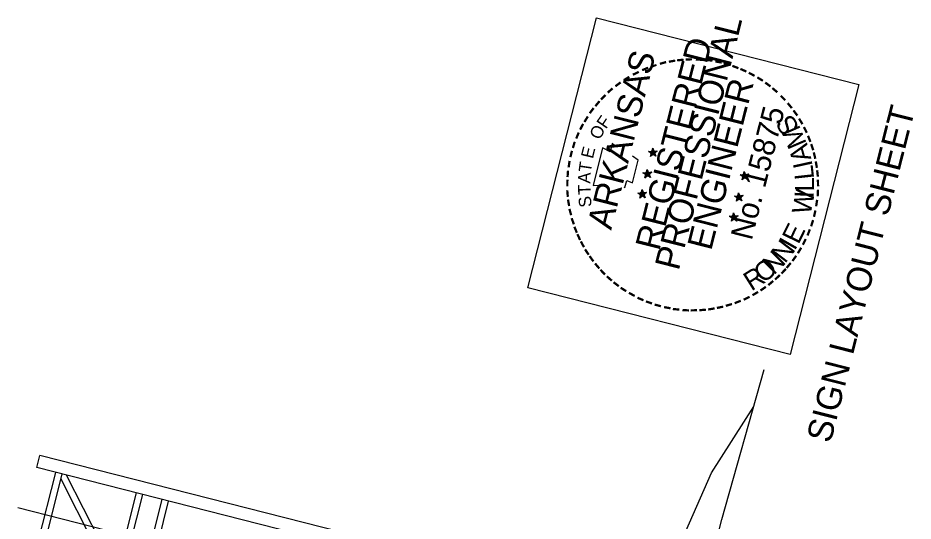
# Model space of a CAD drawing. Extents: x 670006 to 670131, y 737833 to 738003.
# Drawn here: x 670085.91 to 670130.78, y 737959.35 to 737984.55 of the extents above; entities that cross this region are included whole.
import ezdxf

# ---------------------------------------------------------------- set-up
doc = ezdxf.new("R2010")
doc.units = 0
for name, color, linetype in [('R_Border Notes', 7, 'Continuous'), ('R_Border PE', 7, 'Continuous'), ('R_Border Prem', 7, 'Continuous'), ('R_Exist Surface', 7, 'Continuous'), ('R_Fin Surface', 7, 'Continuous'), ('R_SIGN', 7, 'Continuous')]:
    doc.layers.add(name, color=color, linetype=linetype)

msp = doc.modelspace()

# ---------------------------------------------------------------- linework, layer by layer
at = {"layer": 'R_Border PE'}
for p, q in [((670117.518, 737977.86), (670117.681, 737977.864)), ((670117.736, 737977.805), (670117.518, 737977.86)), ((670117.518, 737977.86), (670117.678, 737977.852)), ((670117.518, 737977.86), (670117.667, 737977.836)), ((670117.518, 737977.86), (670117.667, 737977.81)), ((670117.518, 737977.86), (670117.664, 737977.798)), ((670117.518, 737977.86), (670117.655, 737977.787)), ((670117.724, 737978.034), (670117.688, 737977.843)), ((670117.724, 737978.034), (670117.709, 737977.851)), ((670117.724, 737978.034), (670117.721, 737977.848)), ((670117.724, 737978.034), (670117.736, 737977.805)), ((670117.724, 737978.034), (670117.744, 737977.887)), ((670117.724, 737978.034), (670117.752, 737977.891)), ((670117.724, 737978.034), (670117.761, 737977.902)), ((670117.95, 737977.886), (670117.736, 737977.805)), ((670117.95, 737977.886), (670117.755, 737977.852)), ((670117.95, 737977.886), (670117.758, 737977.864)), ((670117.95, 737977.886), (670117.778, 737977.84)), ((670117.95, 737977.886), (670117.785, 737977.793)), ((670117.95, 737977.886), (670117.797, 737977.816)), ((670117.95, 737977.886), (670117.803, 737977.788)), ((670117.616, 737977.61), (670117.736, 737977.805)), ((670117.616, 737977.61), (670117.674, 737977.763)), ((670117.616, 737977.61), (670117.685, 737977.754)), ((670117.616, 737977.61), (670117.691, 737977.752)), ((670117.616, 737977.61), (670117.713, 737977.74)), ((670117.616, 737977.61), (670117.726, 737977.737)), ((670117.616, 737977.61), (670117.738, 737977.734)), ((670117.884, 737977.626), (670117.733, 737977.741)), ((670117.884, 737977.626), (670117.736, 737977.805)), ((670117.884, 737977.626), (670117.753, 737977.743)), ((670117.884, 737977.626), (670117.762, 737977.753)), ((670117.884, 737977.626), (670117.785, 737977.793)), ((670117.884, 737977.626), (670117.785, 737977.767)), ((670117.884, 737977.626), (670117.805, 737977.794)), ((670117.446, 737976.963), (670117.41, 737976.772)), ((670117.446, 737976.963), (670117.431, 737976.78)), ((670117.446, 737976.963), (670117.443, 737976.777)), ((670117.446, 737976.963), (670117.458, 737976.734)), ((670117.446, 737976.963), (670117.466, 737976.816)), ((670117.446, 737976.963), (670117.475, 737976.827)), ((670117.446, 737976.963), (670117.483, 737976.831)), ((670117.234, 737976.791), (670117.403, 737976.794)), ((670117.458, 737976.734), (670117.234, 737976.791)), ((670117.234, 737976.791), (670117.393, 737976.783)), ((670117.234, 737976.791), (670117.389, 737976.765)), ((670117.234, 737976.791), (670117.383, 737976.741)), ((670117.234, 737976.791), (670117.386, 737976.727)), ((670117.234, 737976.791), (670117.378, 737976.722)), ((670117.338, 737976.539), (670117.458, 737976.734)), ((670117.338, 737976.539), (670117.39, 737976.694)), ((670117.338, 737976.539), (670117.402, 737976.691)), ((670117.338, 737976.539), (670117.413, 737976.681)), ((670117.338, 737976.539), (670117.435, 737976.669)), ((670117.338, 737976.539), (670117.448, 737976.666)), ((670117.338, 737976.539), (670117.46, 737976.663)), ((670117.608, 737976.561), (670117.455, 737976.671)), ((670117.674, 737976.822), (670117.458, 737976.734)), ((670117.608, 737976.561), (670117.458, 737976.734)), ((670117.674, 737976.822), (670117.474, 737976.795)), ((670117.608, 737976.561), (670117.475, 737976.672)), ((670117.674, 737976.822), (670117.477, 737976.781)), ((670117.608, 737976.561), (670117.484, 737976.683)), ((670117.674, 737976.822), (670117.499, 737976.769)), ((670117.674, 737976.822), (670117.507, 737976.722)), ((670117.608, 737976.561), (670117.507, 737976.722)), ((670117.608, 737976.561), (670117.507, 737976.696)), ((670117.674, 737976.822), (670117.519, 737976.745)), ((670117.674, 737976.822), (670117.525, 737976.717)), ((670117.608, 737976.561), (670117.527, 737976.724)), ((670122.323, 737976.642), (670122.104, 737976.697)), ((670122.104, 737976.697), (670122.265, 737976.695)), ((670122.104, 737976.697), (670122.264, 737976.689)), ((670122.104, 737976.697), (670122.259, 737976.671)), ((670122.104, 737976.697), (670122.253, 737976.647)), ((670122.104, 737976.697), (670122.25, 737976.635)), ((670122.104, 737976.697), (670122.247, 737976.623)), ((670122.202, 737976.447), (670122.323, 737976.642)), ((670122.202, 737976.447), (670122.259, 737976.594)), ((670122.202, 737976.447), (670122.271, 737976.591)), ((670122.202, 737976.447), (670122.281, 737976.581)), ((670122.202, 737976.447), (670122.3, 737976.577)), ((670122.202, 737976.447), (670122.316, 737976.566)), ((670122.202, 737976.447), (670122.328, 737976.563)), ((670122.308, 737976.865), (670122.274, 737976.68)), ((670122.308, 737976.865), (670122.295, 737976.688)), ((670122.308, 737976.865), (670122.307, 737976.684)), ((670122.308, 737976.865), (670122.323, 737976.642)), ((670122.308, 737976.865), (670122.329, 737976.718)), ((670122.308, 737976.865), (670122.344, 737976.727)), ((670122.308, 737976.865), (670122.352, 737976.731)), ((670122.47, 737976.463), (670122.318, 737976.572)), ((670122.537, 737976.723), (670122.323, 737976.642)), ((670122.47, 737976.463), (670122.323, 737976.642)), ((670122.537, 737976.723), (670122.339, 737976.683)), ((670122.537, 737976.723), (670122.342, 737976.695)), ((670122.47, 737976.463), (670122.343, 737976.572)), ((670122.47, 737976.463), (670122.354, 737976.589)), ((670122.537, 737976.723), (670122.368, 737976.669)), ((670122.47, 737976.463), (670122.371, 737976.604)), ((670122.537, 737976.723), (670122.375, 737976.622)), ((670122.47, 737976.463), (670122.375, 737976.622)), ((670122.537, 737976.723), (670122.382, 737976.646)), ((670122.47, 737976.463), (670122.389, 737976.625)), ((670122.537, 737976.723), (670122.394, 737976.617)), ((670116.978, 737975.779), (670117.146, 737975.782)), ((670117.202, 737975.723), (670116.978, 737975.779)), ((670116.978, 737975.779), (670117.137, 737975.771)), ((670116.978, 737975.779), (670117.134, 737975.759)), ((670116.978, 737975.779), (670117.128, 737975.735)), ((670116.978, 737975.779), (670117.129, 737975.715)), ((670116.978, 737975.779), (670117.121, 737975.711)), ((670117.081, 737975.527), (670117.202, 737975.723)), ((670117.081, 737975.527), (670117.133, 737975.682)), ((670117.081, 737975.527), (670117.146, 737975.679)), ((670117.081, 737975.527), (670117.156, 737975.67)), ((670117.081, 737975.527), (670117.18, 737975.664)), ((670117.081, 737975.527), (670117.191, 737975.654)), ((670117.081, 737975.527), (670117.203, 737975.651)), ((670117.189, 737975.952), (670117.153, 737975.761)), ((670117.189, 737975.952), (670117.175, 737975.768)), ((670117.189, 737975.952), (670117.187, 737975.765)), ((670117.189, 737975.952), (670117.202, 737975.723)), ((670117.189, 737975.952), (670117.21, 737975.804)), ((670117.189, 737975.952), (670117.219, 737975.815)), ((670117.189, 737975.952), (670117.226, 737975.82)), ((670117.351, 737975.549), (670117.199, 737975.659)), ((670117.417, 737975.81), (670117.202, 737975.723)), ((670117.351, 737975.549), (670117.202, 737975.723)), ((670117.417, 737975.81), (670117.217, 737975.783)), ((670117.351, 737975.549), (670117.218, 737975.66)), ((670117.417, 737975.81), (670117.22, 737975.77)), ((670117.351, 737975.549), (670117.227, 737975.671)), ((670117.417, 737975.81), (670117.243, 737975.757)), ((670117.417, 737975.81), (670117.25, 737975.71)), ((670117.351, 737975.549), (670117.25, 737975.71)), ((670117.351, 737975.549), (670117.25, 737975.685)), ((670117.417, 737975.81), (670117.263, 737975.733)), ((670117.417, 737975.81), (670117.268, 737975.706)), ((670117.351, 737975.549), (670117.27, 737975.712)), ((670122.044, 737975.571), (670121.826, 737975.627)), ((670121.826, 737975.627), (670121.987, 737975.624)), ((670121.826, 737975.627), (670121.986, 737975.618)), ((670121.826, 737975.627), (670121.981, 737975.6)), ((670121.826, 737975.627), (670121.975, 737975.576)), ((670121.826, 737975.627), (670121.972, 737975.564)), ((670121.826, 737975.627), (670121.963, 737975.553)), ((670121.924, 737975.376), (670122.044, 737975.571)), ((670122.03, 737975.794), (670121.996, 737975.609)), ((670122.03, 737975.794), (670122.017, 737975.617)), ((670122.03, 737975.794), (670122.029, 737975.614)), ((670122.03, 737975.794), (670122.044, 737975.571)), ((670122.03, 737975.794), (670122.051, 737975.647)), ((670122.03, 737975.794), (670122.06, 737975.658)), ((670122.03, 737975.794), (670122.075, 737975.667)), ((670122.259, 737975.652), (670122.044, 737975.571)), ((670122.192, 737975.392), (670122.044, 737975.571)), ((670122.259, 737975.652), (670122.061, 737975.612)), ((670122.259, 737975.652), (670122.066, 737975.63)), ((670122.259, 737975.652), (670122.086, 737975.606)), ((670122.259, 737975.652), (670122.099, 737975.557)), ((670122.259, 737975.652), (670122.104, 737975.576)), ((670122.259, 737975.652), (670122.11, 737975.548)), ((670121.924, 737975.376), (670121.981, 737975.523)), ((670121.924, 737975.376), (670121.993, 737975.52)), ((670121.924, 737975.376), (670121.999, 737975.518)), ((670121.924, 737975.376), (670122.022, 737975.506)), ((670121.924, 737975.376), (670122.034, 737975.503)), ((670121.924, 737975.376), (670122.046, 737975.5)), ((670122.192, 737975.392), (670122.041, 737975.508)), ((670122.192, 737975.392), (670122.067, 737975.507)), ((670122.192, 737975.392), (670122.076, 737975.518)), ((670122.192, 737975.392), (670122.093, 737975.559)), ((670122.192, 737975.392), (670122.093, 737975.533)), ((670122.192, 737975.392), (670122.111, 737975.554)), ((670121.775, 737974.788), (670121.74, 737974.598)), ((670121.775, 737974.788), (670121.761, 737974.605)), ((670121.775, 737974.788), (670121.773, 737974.602)), ((670121.775, 737974.788), (670121.788, 737974.559)), ((670121.775, 737974.788), (670121.794, 737974.635)), ((670121.775, 737974.788), (670121.803, 737974.646)), ((670121.775, 737974.788), (670121.819, 737974.655)), ((670121.57, 737974.615), (670121.732, 737974.619)), ((670121.788, 737974.559), (670121.57, 737974.615)), ((670121.57, 737974.615), (670121.729, 737974.607)), ((670121.57, 737974.615), (670121.724, 737974.589)), ((670121.57, 737974.615), (670121.718, 737974.564)), ((670121.57, 737974.615), (670121.715, 737974.552)), ((670121.57, 737974.615), (670121.706, 737974.542)), ((670121.667, 737974.364), (670121.788, 737974.559)), ((670121.667, 737974.364), (670121.726, 737974.517)), ((670121.667, 737974.364), (670121.736, 737974.508)), ((670121.667, 737974.364), (670121.742, 737974.507)), ((670121.667, 737974.364), (670121.765, 737974.494)), ((670121.667, 737974.364), (670121.777, 737974.491)), ((670121.667, 737974.364), (670121.789, 737974.488)), ((670121.936, 737974.38), (670121.785, 737974.496)), ((670122.002, 737974.641), (670121.788, 737974.559)), ((670121.936, 737974.38), (670121.788, 737974.559)), ((670122.002, 737974.641), (670121.805, 737974.6)), ((670122.002, 737974.641), (670121.809, 737974.619)), ((670121.936, 737974.38), (670121.81, 737974.496)), ((670121.936, 737974.38), (670121.82, 737974.506)), ((670122.002, 737974.641), (670121.829, 737974.594)), ((670121.936, 737974.38), (670121.836, 737974.547)), ((670121.936, 737974.38), (670121.836, 737974.521)), ((670122.002, 737974.641), (670121.842, 737974.546)), ((670122.002, 737974.641), (670121.847, 737974.564)), ((670122.002, 737974.641), (670121.853, 737974.537)), ((670121.936, 737974.38), (670121.855, 737974.543))]:
    msp.add_line(p, q, dxfattribs=at)
for points in [[(670115.835, 737978.139), (670115.687, 737978.267), (670115.593, 737977.846), (670115.216, 737978.038), (670114.739, 737976.154)], [(670117.518, 737977.86), (670117.95, 737977.886), (670117.616, 737977.61), (670117.724, 737978.034), (670117.884, 737977.626), (670117.518, 737977.86)], [(670116.28, 737976.079), (670116.334, 737976.065), (670116.433, 737976.401), (670116.71, 737976.299), (670116.997, 737977.432), (670116.707, 737977.634)], [(670117.234, 737976.791), (670117.674, 737976.822), (670117.338, 737976.539), (670117.446, 737976.963), (670117.608, 737976.561), (670117.234, 737976.791)], [(670122.104, 737976.697), (670122.537, 737976.723), (670122.202, 737976.447), (670122.308, 737976.865), (670122.47, 737976.463), (670122.104, 737976.697)], [(670114.739, 737976.154), (670115.281, 737976.184)], [(670116.978, 737975.779), (670117.417, 737975.81), (670117.081, 737975.527), (670117.189, 737975.952), (670117.351, 737975.549), (670116.978, 737975.779)], [(670121.826, 737975.627), (670122.259, 737975.652), (670121.924, 737975.376), (670122.03, 737975.794), (670122.192, 737975.392), (670121.826, 737975.627)], [(670121.57, 737974.615), (670122.002, 737974.641), (670121.667, 737974.364), (670121.775, 737974.788), (670121.936, 737974.38), (670121.57, 737974.615)]]:
    msp.add_lwpolyline(points, dxfattribs=at)
for centre, radius in [((670117.738, 737977.804), 0.108), ((670117.738, 737977.804), 0.0975), ((670117.738, 737977.804), 0.0904), ((670117.738, 737977.804), 0.083), ((670117.738, 737977.804), 0.0723), ((670117.738, 737977.804), 0.0672), ((670117.738, 737977.804), 0.0619), ((670117.738, 737977.804), 0.0533), ((670117.738, 737977.804), 0.0467), ((670117.738, 737977.804), 0.0388), ((670117.738, 737977.804), 0.031), ((670117.738, 737977.804), 0.0231), ((670117.738, 737977.804), 0.0185), ((670117.738, 737977.804), 0.00901), ((670117.459, 737976.735), 0.108), ((670117.459, 737976.735), 0.0975), ((670117.459, 737976.735), 0.0904), ((670117.459, 737976.735), 0.083), ((670117.459, 737976.735), 0.0723), ((670117.459, 737976.735), 0.0672), ((670117.459, 737976.735), 0.0619), ((670117.459, 737976.735), 0.0533), ((670117.459, 737976.735), 0.0467), ((670117.459, 737976.735), 0.0388), ((670117.459, 737976.735), 0.031), ((670117.459, 737976.735), 0.0231), ((670117.459, 737976.735), 0.0185), ((670117.459, 737976.735), 0.00901), ((670122.325, 737976.638), 0.108), ((670122.325, 737976.638), 0.0975), ((670122.325, 737976.638), 0.0904), ((670122.325, 737976.638), 0.083), ((670122.325, 737976.638), 0.0723), ((670122.325, 737976.638), 0.0672), ((670122.325, 737976.638), 0.0619), ((670122.325, 737976.638), 0.0533), ((670122.325, 737976.638), 0.0467), ((670122.325, 737976.638), 0.0388), ((670122.325, 737976.638), 0.031), ((670122.325, 737976.638), 0.0231), ((670122.325, 737976.638), 0.0185), ((670122.325, 737976.638), 0.00901), ((670117.203, 737975.724), 0.108), ((670117.203, 737975.724), 0.0975), ((670117.203, 737975.724), 0.0904), ((670117.203, 737975.724), 0.083), ((670117.203, 737975.724), 0.0723), ((670117.203, 737975.724), 0.0672), ((670117.203, 737975.724), 0.0619), ((670117.203, 737975.724), 0.0533), ((670117.203, 737975.724), 0.0467), ((670117.203, 737975.724), 0.0388), ((670117.203, 737975.724), 0.031), ((670117.203, 737975.724), 0.0231), ((670117.203, 737975.724), 0.0185), ((670117.203, 737975.724), 0.00901), ((670122.047, 737975.569), 0.108), ((670122.047, 737975.569), 0.0975), ((670122.047, 737975.569), 0.0904), ((670122.047, 737975.569), 0.083), ((670122.047, 737975.569), 0.0723), ((670122.047, 737975.569), 0.0672), ((670122.047, 737975.569), 0.0619), ((670122.047, 737975.569), 0.0533), ((670122.047, 737975.569), 0.0467), ((670122.047, 737975.569), 0.0388), ((670122.047, 737975.569), 0.031), ((670122.047, 737975.569), 0.0231), ((670122.047, 737975.569), 0.0185), ((670122.047, 737975.569), 0.00901), ((670121.79, 737974.558), 0.108), ((670121.79, 737974.558), 0.0975), ((670121.79, 737974.558), 0.0904), ((670121.79, 737974.558), 0.083), ((670121.79, 737974.558), 0.0723), ((670121.79, 737974.558), 0.0672), ((670121.79, 737974.558), 0.0619), ((670121.79, 737974.558), 0.0533), ((670121.79, 737974.558), 0.0467), ((670121.79, 737974.558), 0.0388), ((670121.79, 737974.558), 0.031), ((670121.79, 737974.558), 0.0231), ((670121.79, 737974.558), 0.0185), ((670121.79, 737974.558), 0.00901)]:
    msp.add_circle(centre, radius, dxfattribs=at)
at = {"layer": 'R_Border Prem'}
msp.add_lwpolyline([(670111.474, 737971.03), (670114.904, 737984.552), (670128.049, 737981.218), (670124.62, 737967.696)], close=True, dxfattribs=at)
at = {"layer": 'R_Exist Surface'}
msp.add_lwpolyline([(670120.554, 737956.943), (670121.191, 737959.427), (670123.317, 737966.939)], dxfattribs=at)
at = {"layer": 'R_Fin Surface'}
msp.add_lwpolyline([(670107.159, 737921.866), (670110.341, 737933.439), (670113.187, 737943.034), (670114.744, 737948.282), (670119.014, 737958.012), (670120.664, 737961.771), (670122.794, 737965.094)], dxfattribs=at)
at = {"layer": 'R_SIGN'}
for p, q in [((670086.85, 737962.029), (670087.003, 737962.635)), ((670116.089, 737955.258), (670087.003, 737962.635)), ((670086.731, 737957.546), (670087.807, 737961.786)), ((670115.935, 737954.652), (670086.85, 737962.029)), ((670087.054, 737957.464), (670088.13, 737961.704)), ((670090.551, 737956.577), (670088.066, 737961.454)), ((670090.833, 737956.771), (670088.349, 737961.649)), ((670090.77, 737956.521), (670091.845, 737960.762)), ((670091.093, 737956.439), (670092.168, 737960.68)), ((670092.062, 737956.193), (670093.138, 737960.434)), ((670092.385, 737956.112), (670093.461, 737960.352)), ((670115.397, 737952.532), (670085.905, 737960.012))]:
    msp.add_line(p, q, dxfattribs=at)

# ---------------------------------------------------------------- texts
at = {"layer": 'R_Border Notes'}
msp.add_text('SIGN LAYOUT SHEET', height=1.25, rotation=75.7686, dxfattribs=at).set_placement((670126.637, 737963.215))
at = {"layer": 'R_Border PE'}
for s, height, rotation, p in [('PROFESSIONAL', 1.24999, 75.7686, (670119.026, 737971.856)), ('REGISTERED', 1.25, 75.7686, (670118.052, 737972.844)), ('ARKANSAS', 1.25, 75.7686, (670115.642, 737973.894)), ('-', 1, 15.4369, (670118.128, 737981.865)), ('-', 1, 10.4313, (670118.546, 737981.965)), ('-', 1, 6.3414, (670118.932, 737982.035)), ('-', 1, 0.8918, (670119.318, 737982.085)), ('-', 1, 356.3179, (670119.804, 737982.091)), ('-', 1, 352.3647, (670120.29, 737982.077)), ('-', 1, 350.0987, (670120.742, 737982.001)), ('-', 1, 345.7092, (670121.128, 737981.923)), ('-', 1, 25.6483, (670116.845, 737981.333)), ('-', 1, 22.4207, (670117.288, 737981.555)), ('-', 0.875, 19.4438, (670117.709, 737981.765)), ('-', 1, 339.2857, (670121.525, 737981.809)), ('-', 1, 336.7638, (670121.914, 737981.665)), ('-', 1, 331.5312, (670122.309, 737981.494)), ('-', 1, 31.3471, (670116.424, 737981.072)), ('ENGINEER', 1.25, 75.7686, (670120.653, 737972.855)), ('-', 1, 328.6366, (670122.717, 737981.275)), ('-', 1, 41.6312, (670115.681, 737980.48)), ('-', 1, 36.2983, (670116.035, 737980.783)), ('-', 1, 323.6572, (670123.089, 737981.038)), ('-', 1, 320.3883, (670123.43, 737980.778)), ('-', 1, 45.4094, (670115.365, 737980.148)), ('-', 1, 314.8398, (670123.824, 737980.427)), ('-', 1, 53.6236, (670114.845, 737979.499)), ('-', 1, 49.8896, (670115.106, 737979.839)), ('No. 15875', 1.1, 75.7686, (670122.685, 737973.37)), ('-', 1, 309.6138, (670124.156, 737980.084)), ('-', 1, 58.1047, (670114.598, 737979.085)), ('F', 0.625, 55.8392, (670115.385, 737978.956)), ('S', 0.962, 121.462, (670125.108, 737979.057)), ('-', 1, 307.0223, (670124.436, 737979.736)), ('-', 1, 62.9734, (670114.405, 737978.727)), ('M', 0.962, 113.3256, (670125.46, 737978.268)), ('-', 1, 301.5339, (670124.701, 737979.359)), ('-', 1, 67.9303, (670114.227, 737978.308)), ('O', 0.625, 66.2201, (670115.099, 737978.416)), ('-', 1, 296.8536, (670124.93, 737978.966)), ('-', 1, 73.5116, (670114.077, 737977.869)), ('A', 0.962, 105.7601, (670125.685, 737977.495)), ('-', 1, 291.5049, (670125.13, 737978.561)), ('-', 1, 75.9548, (670113.959, 737977.428)), ('E', 0.625, 76.6009, (670114.725, 737977.473)), ('-', 1, 288.0176, (670125.284, 737978.174)), ('-', 1, 283.1254, (670125.411, 737977.787)), ('-', 1, 81.6654, (670113.883, 737976.951)), ('T', 0.625, 81.7913, (670114.622, 737976.789)), ('I', 0.962, 102.3343, (670125.752, 737977.138)), ('-', 1, 280.0202, (670125.508, 737977.356)), ('L', 0.962, 96.339, (670125.819, 737976.504)), ('-', 1, 276.487, (670125.577, 737976.939)), ('-', 1, 85.9879, (670113.838, 737976.492)), ('A', 0.625, 86.9817, (670114.595, 737976.248)), ('L', 0.962, 90.3438, (670125.819, 737975.866)), ('-', 1, 89.3987, (670113.83, 737976.055)), ('T', 0.625, 92.1721, (670114.619, 737975.707)), ('W', 0.962, 78.7816, (670125.631, 737974.653)), ('-', 1, 271.2428, (670125.619, 737976.496)), ('-', 1, 94.9446, (670113.86, 737975.564)), ('S', 0.625, 97.3626, (670114.679, 737975.105)), ('I', 0.962, 86.9179, (670125.789, 737975.503)), ('-', 1, 267.0543, (670125.628, 737976.023)), ('-', 1, 100.0758, (670113.927, 737975.141)), ('-', 1, 261.5852, (670125.593, 737975.555)), ('-', 1, 104.5604, (670114.024, 737974.71)), ('-', 1, 257.3603, (670125.517, 737975.052)), ('-', 1, 109.8321, (670114.156, 737974.29)), ('E', 0.962, 63.7221, (670125.03, 737973.173)), ('-', 1, 252.2868, (670125.415, 737974.6)), ('-', 1, 112.0003, (670114.303, 737973.879)), ('-', 1, 248.884, (670125.264, 737974.155)), ('-', 1, 114.7192, (670114.461, 737973.535)), ('-', 1, 118.7308, (670114.648, 737973.204)), ('N', 0.962, 52.7308, (670124.359, 737972.219)), ('I', 0.962, 60.2962, (670124.841, 737972.862)), ('-', 1, 243.3241, (670125.079, 737973.705)), ('-', 1, 124.1916, (670114.87, 737972.858)), ('N', 0.962, 45.1654, (670123.796, 737971.644)), ('-', 1, 238.5668, (670124.871, 737973.294)), ('-', 1, 126.3827, (670115.099, 737972.542)), ('-', 1, 234.3298, (670124.64, 737972.914)), ('-', 1, 130.001, (670115.381, 737972.206)), ('-', 1, 133.8392, (670115.652, 737971.925)), ('R', 0.962, 32.1757, (670122.671, 737970.847)), ('O', 0.962, 38.8847, (670123.275, 737971.227)), ('-', 1, 227.3389, (670124.16, 737972.294)), ('-', 1, 230.3687, (670124.385, 737972.572)), ('-', 1, 138.6399, (670115.974, 737971.643)), ('-', 1, 223.8583, (670123.871, 737971.994)), ('-', 1, 143.5428, (670116.303, 737971.392)), ('-', 1, 148.163, (670116.651, 737971.162)), ('-', 1, 214.7024, (670123.226, 737971.435)), ('-', 1, 220.4149, (670123.561, 737971.711)), ('-', 1, 151.2295, (670117.058, 737970.936)), ('-', 1, 206.4867, (670122.461, 737970.959)), ('-', 1, 209.9924, (670122.868, 737971.191)), ('-', 1, 156.9698, (670117.467, 737970.742)), ('-', 1, 160.9549, (670117.874, 737970.594)), ('-', 1, 164.8308, (670118.294, 737970.468)), ('-', 1, 196.2157, (670121.65, 737970.61)), ('-', 1, 201.662, (670122.051, 737970.766)), ('-', 1, 169.9644, (670118.742, 737970.38)), ('-', 1, 174.7165, (670119.153, 737970.321)), ('-', 1, 177.4835, (670119.621, 737970.286)), ('-', 1, 181.2264, (670120.004, 737970.298)), ('-', 1, 184.856, (670120.418, 737970.329)), ('-', 1, 189.8329, (670120.822, 737970.394)), ('-', 1, 191.4974, (670121.243, 737970.481))]:
    msp.add_text(s, height=height, rotation=rotation, dxfattribs=at).set_placement(p)

doc.saveas('drawing.dxf')
